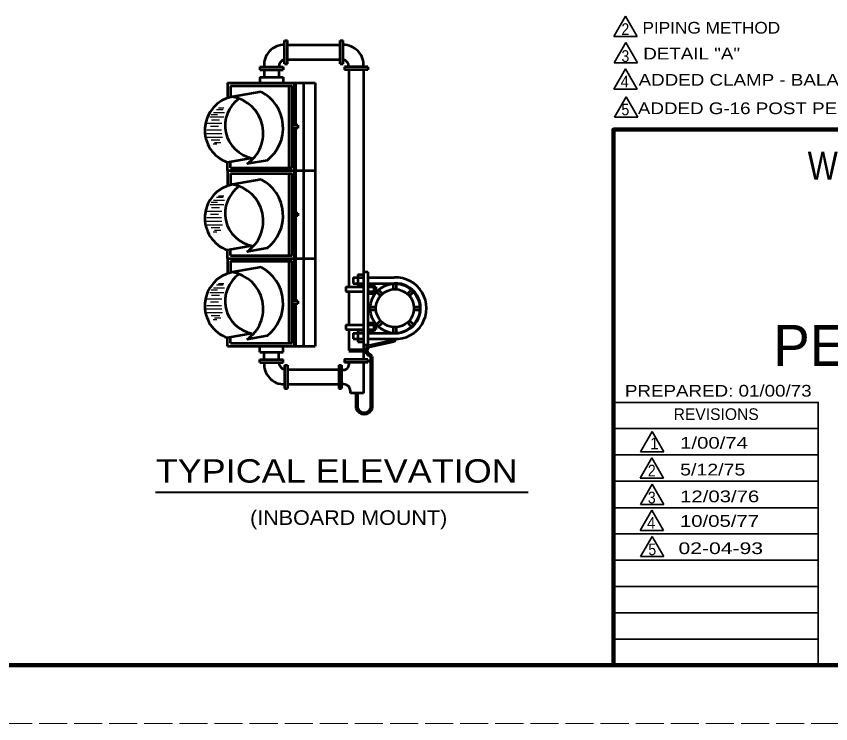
# Model space of a CAD drawing. Extents: x -286 to 394, y -156 to 284.
# Drawn here: x 109 to 248.2, y -155.6 to -34.6 of the extents above; entities that cross this region are included whole.
import ezdxf
from ezdxf.enums import TextEntityAlignment as Align

# ---------------------------------------------------------------- set-up
doc = ezdxf.new("R2010")
doc.units = 0
doc.header["$LTSCALE"] = 0.8
doc.linetypes.add('LONG_DASHED', pattern=[7.5, 6, -1.5])
doc.layers.add('1', color=7, linetype='Continuous', lineweight=53)
doc.layers.add('61', color=7, linetype='Continuous', lineweight=35)

msp = doc.modelspace()

# ---------------------------------------------------------------- linework, layer by layer
at = {"layer": '1', "lineweight": 35}
for p, q in [((213.1055, -34.6416), (211.1055, -38.1057)), ((213.1055, -34.6416), (215.1055, -38.1057)), ((211.1055, -38.1057), (215.1055, -38.1057)), ((213.1387, -39.1506), (211.1387, -42.6147)), ((213.1387, -39.1506), (215.1387, -42.6147)), ((211.1387, -42.6147), (215.1387, -42.6147)), ((213.1055, -43.6264), (211.1055, -47.0905)), ((213.1055, -43.6264), (215.1055, -47.0905)), ((211.1055, -47.0905), (215.1055, -47.0905)), ((213.203, -48.403), (211.203, -51.8671)), ((213.203, -48.403), (215.203, -51.8671)), ((211.203, -51.8671), (215.203, -51.8671)), ((246.0509, -105.1372), (211.0709, -105.1372)), ((217.6545, -105.633), (215.6545, -109.0971)), ((217.6545, -105.633), (219.6545, -109.0971)), ((246.0509, -109.6372), (211.0709, -109.6372)), ((215.6545, -109.0971), (219.6545, -109.0971)), ((217.6214, -110.1088), (215.6214, -113.5729)), ((217.6214, -110.1088), (219.6214, -113.5729)), ((246.0509, -114.1372), (211.0709, -114.1372)), ((215.6214, -113.5729), (219.6214, -113.5729)), ((217.6547, -114.6178), (215.6547, -118.0819)), ((217.6547, -114.6178), (219.6547, -118.0819)), ((215.6547, -118.0819), (219.6547, -118.0819)), ((246.0509, -118.6572), (211.0709, -118.6572)), ((217.6214, -119.0937), (215.6214, -122.5577)), ((217.6214, -119.0937), (219.6214, -122.5577)), ((246.0509, -123.1372), (211.0709, -123.1372)), ((215.6214, -122.5577), (219.6214, -122.5577)), ((217.6825, -123.5532), (215.6825, -127.0173)), ((217.6825, -123.5532), (219.6825, -127.0173)), ((246.0509, -127.6172), (211.0709, -127.6172)), ((215.6825, -127.0173), (219.6825, -127.0173)), ((246.0509, -132.1172), (211.0709, -132.1172)), ((246.0509, -136.6172), (211.0709, -136.6172)), ((246.0509, -141.1372), (211.0709, -141.1372))]:
    msp.add_line(p, q, dxfattribs=at)
at = {"layer": '1'}
for p, q in [((154.826, -42.7785), (154.826, -38.7785)), ((154.826, -38.7785), (155.326, -38.7785)), ((155.326, -42.7785), (155.326, -38.7785)), ((164.326, -42.7785), (164.326, -38.7785)), ((164.326, -42.7785), (164.326, -38.7785)), ((164.326, -38.7785), (164.826, -38.7785)), ((164.826, -42.7785), (164.826, -38.7785)), ((155.326, -39.5285), (164.326, -39.5285)), ((154.826, -42.7785), (155.326, -42.7785)), ((155.326, -42.0285), (164.326, -42.0285)), ((164.326, -42.7785), (164.826, -42.7785)), ((150.576, -43.2785), (154.576, -43.2785)), ((150.576, -43.2785), (150.576, -43.7785)), ((150.576, -43.7785), (154.576, -43.7785)), ((151.326, -43.7785), (151.326, -45.0285)), ((153.826, -43.7785), (153.826, -45.0285)), ((154.576, -43.2785), (154.576, -43.7785)), ((169.076, -43.2785), (165.076, -43.2785)), ((165.076, -43.2785), (165.076, -43.7785)), ((169.076, -43.7785), (165.076, -43.7785)), ((165.826, -43.7785), (165.826, -80.9017)), ((168.326, -43.7785), (168.326, -93.3017)), ((169.076, -43.2785), (169.076, -43.7785)), ((150.576, -45.0285), (154.576, -45.0285)), ((150.576, -45.0285), (150.576, -46.0285)), ((154.576, -45.0285), (154.576, -46.0285)), ((145.076, -46.0285), (160.076, -46.0285)), ((145.076, -46.0285), (145.076, -48.5944)), ((145.576, -46.5285), (156.076, -46.5285)), ((145.576, -46.5285), (145.576, -48.4608)), ((155.576, -46.5285), (155.576, -60.5285)), ((156.076, -46.5285), (156.076, -60.5285)), ((158.076, -46.0285), (158.076, -91.0285)), ((160.076, -46.0285), (160.076, -91.0285)), ((150.826, -47.5285), (145.902, -48.3967)), ((157.076, -53.2785), (156.076, -53.2785)), ((157.076, -53.7785), (156.076, -53.7785)), ((157.076, -53.2785), (157.076, -53.7785)), ((149.247, -58.8807), (145.076, -59.6162)), ((145.076, -61.0285), (145.076, -59.6162)), ((145.576, -60.5285), (145.576, -59.528)), ((151.826, -59.2785), (148.3792, -59.8862)), ((145.076, -61.0285), (160.076, -61.0285)), ((145.076, -61.0285), (145.076, -63.6202)), ((145.576, -60.5285), (156.076, -60.5285)), ((145.576, -61.5285), (156.076, -61.5285)), ((145.576, -61.5285), (145.576, -63.4694)), ((150.826, -62.5285), (145.902, -63.3967)), ((155.576, -61.5285), (155.576, -75.5285)), ((156.076, -61.5285), (156.076, -75.5285)), ((157.076, -68.2785), (156.076, -68.2785)), ((157.076, -68.7785), (156.076, -68.7785)), ((157.076, -68.2785), (157.076, -68.7785)), ((149.247, -73.8807), (145.076, -74.6162)), ((145.076, -76.0285), (145.076, -74.6162)), ((145.576, -75.5285), (145.576, -74.528)), ((151.826, -74.2785), (148.3792, -74.8863)), ((145.076, -76.0285), (160.076, -76.0285)), ((145.076, -76.0285), (145.076, -78.6202)), ((145.576, -75.5285), (156.076, -75.5285)), ((145.576, -76.5285), (156.076, -76.5285)), ((145.576, -76.5285), (145.576, -78.4694)), ((155.576, -76.5285), (155.576, -90.5285)), ((156.076, -76.5285), (156.076, -90.5285)), ((150.826, -77.5285), (145.902, -78.3967)), ((166.576, -79.3017), (166.576, -80.3017)), ((166.576, -79.3017), (168.326, -79.3017)), ((167.326, -78.8017), (168.326, -78.8017)), ((167.326, -78.8017), (167.326, -80.8017)), ((168.326, -78.3017), (169.076, -78.3017)), ((169.076, -78.3017), (169.076, -90.8017)), ((169.076, -79.3017), (173.576, -79.3017)), ((166.576, -80.3017), (168.326, -80.3017)), ((169.076, -80.3017), (173.576, -80.3017)), ((169.076, -80.5517), (170.076, -80.5517)), ((170.076, -80.5517), (170.076, -82.0517)), ((173.4597, -81.3007), (173.4597, -80.3228)), ((173.9597, -81.3007), (173.9597, -80.3228)), ((165.326, -80.9017), (168.326, -80.9017)), ((165.326, -80.9017), (165.326, -81.7017)), ((165.326, -81.7017), (168.326, -81.7017)), ((165.826, -81.7017), (165.826, -87.4017)), ((167.326, -80.8017), (168.326, -80.8017)), ((169.076, -80.9017), (170.426, -80.9017)), ((169.076, -81.7017), (170.426, -81.7017)), ((169.076, -82.0517), (170.076, -82.0517)), ((170.426, -80.9017), (170.426, -81.7017)), ((171.2233, -82.4184), (170.5351, -81.7303)), ((171.5768, -82.0648), (170.8887, -81.3768)), ((175.8154, -82.0815), (176.5245, -81.3763)), ((176.168, -82.4361), (176.8771, -81.7309)), ((157.076, -83.2785), (156.076, -83.2785)), ((157.076, -83.2785), (157.076, -83.7785)), ((157.076, -83.7785), (156.076, -83.7785)), ((169.4597, -84.3017), (170.4373, -84.3017)), ((169.4597, -84.8017), (170.4373, -84.8017)), ((176.9373, -84.3017), (177.9596, -84.3017)), ((176.9373, -84.8017), (177.9596, -84.8017)), ((165.326, -87.4017), (168.326, -87.4017)), ((165.326, -87.4017), (165.326, -88.2017)), ((169.076, -87.0517), (170.076, -87.0517)), ((169.076, -87.4017), (170.426, -87.4017)), ((170.076, -87.0517), (170.076, -88.5517)), ((170.426, -87.4017), (170.426, -88.2017)), ((170.4977, -87.37), (171.2066, -86.665)), ((170.8502, -87.7246), (171.5592, -87.0196)), ((176.5496, -87.7433), (175.8201, -87.014)), ((176.903, -87.3897), (176.1735, -86.6604)), ((149.247, -88.8807), (145.076, -89.6162)), ((165.326, -88.2017), (168.326, -88.2017)), ((165.826, -88.2017), (165.826, -91.7998)), ((166.576, -88.8017), (166.576, -89.8017)), ((166.576, -88.8017), (168.326, -88.8017)), ((167.326, -88.3017), (167.326, -90.3017)), ((167.326, -88.3017), (168.326, -88.3017)), ((169.076, -88.2017), (170.426, -88.2017)), ((169.076, -88.5517), (170.076, -88.5517)), ((169.076, -88.8017), (173.576, -88.8017)), ((173.4597, -88.8228), (173.4597, -87.8005)), ((173.9597, -88.8228), (173.9597, -87.8005)), ((145.076, -91.0285), (145.076, -89.6162)), ((145.576, -90.5285), (145.576, -89.528)), ((151.826, -89.2785), (148.3792, -89.8863)), ((166.576, -89.8017), (168.326, -89.8017)), ((167.326, -90.3017), (168.326, -90.3017)), ((169.076, -89.8017), (173.576, -89.8017)), ((145.076, -91.0285), (160.076, -91.0285)), ((145.576, -90.5285), (156.076, -90.5285)), ((150.576, -92.0495), (150.576, -91.0495)), ((154.576, -92.0495), (154.576, -91.0495)), ((168.326, -90.8017), (169.076, -90.8017)), ((150.576, -92.0495), (154.576, -92.0495)), ((151.326, -93.2995), (151.326, -92.0495)), ((153.826, -93.2995), (153.826, -92.0495)), ((150.576, -93.2995), (154.576, -93.2995)), ((150.576, -93.7995), (150.576, -93.2995)), ((150.576, -93.7995), (154.576, -93.7995)), ((154.576, -93.7995), (154.576, -93.2995)), ((154.826, -94.2995), (154.826, -98.2995)), ((154.826, -94.2995), (155.326, -94.2995)), ((155.326, -94.2995), (155.326, -98.2995)), ((164.0757, -94.2993), (164.0757, -98.2993)), ((164.0757, -94.2993), (164.5757, -94.2993)), ((164.5757, -94.2993), (164.5757, -98.2993)), ((169.0757, -93.8021), (165.0757, -93.7993)), ((168.3257, -93.8016), (168.3222, -99.0514)), ((169.076, -93.3022), (169.0757, -93.8021)), ((155.326, -95.0495), (164.0757, -95.0495)), ((154.826, -98.2995), (155.326, -98.2995)), ((155.326, -97.5495), (164.0757, -97.5495)), ((164.0757, -98.2993), (164.5757, -98.2993)), ((168.3222, -99.0514), (166.0722, -99.0514))]:
    msp.add_line(p, q, dxfattribs=at)
at = {"layer": '1', "lineweight": 90}
for p, q in [((156.576, -46.0285), (156.576, -53.2785)), ((156.576, -53.7785), (156.576, -68.2785)), ((156.576, -68.7785), (156.576, -83.2785)), ((156.576, -83.7785), (156.576, -91.0285))]:
    msp.add_line(p, q, dxfattribs=at)
at = {"layer": '1', "lineweight": 25}
for p, q in [((142.299, -51.4111), (143.3644, -51.4111)), ((142.6637, -51.0767), (144.5599, -51.0767)), ((143.1803, -50.5598), (144.3417, -50.5598)), ((143.5147, -50.3167), (144.4612, -50.3167)), ((142.0559, -51.8367), (144.4334, -51.8367)), ((142.3294, -52.3231), (143.7277, -52.3231)), ((141.5088, -54.056), (144.033, -54.056)), ((141.5392, -52.9312), (144.1253, -52.9312)), ((142.1774, -53.4479), (143.515, -53.4479)), ((141.4177, -54.664), (144.0923, -54.664)), ((141.4177, -55.3024), (144.2336, -55.3024)), ((142.2498, -55.7762), (143.7624, -55.7762)), ((142.6457, -56.4692), (143.2396, -56.4692)), ((142.8189, -56.197), (143.9368, -56.197)), ((143.5147, -65.3167), (144.4612, -65.3167)), ((142.299, -66.4111), (143.3644, -66.4111)), ((142.6637, -66.0767), (144.5599, -66.0767)), ((143.1803, -65.5598), (144.3417, -65.5598)), ((141.5392, -67.9312), (144.1253, -67.9312)), ((142.0559, -66.8367), (144.4334, -66.8367)), ((142.3294, -67.3231), (143.7277, -67.3231)), ((141.5088, -69.056), (144.033, -69.056)), ((142.1774, -68.4479), (143.515, -68.4479)), ((141.4177, -69.664), (144.0923, -69.664)), ((141.4177, -70.3024), (144.2336, -70.3024)), ((142.2498, -70.7763), (143.7624, -70.7763)), ((142.6457, -71.4693), (143.2396, -71.4693)), ((142.8189, -71.197), (143.9368, -71.197)), ((143.1803, -80.5598), (144.3417, -80.5598)), ((143.5147, -80.3167), (144.4612, -80.3167)), ((142.0559, -81.8367), (144.4334, -81.8367)), ((142.299, -81.4111), (143.3644, -81.4111)), ((142.6637, -81.0767), (144.5599, -81.0767)), ((141.5392, -82.9312), (144.1253, -82.9312)), ((142.1774, -83.4479), (143.515, -83.4479)), ((142.3294, -82.3231), (143.7277, -82.3231)), ((141.4177, -84.664), (144.0923, -84.664)), ((141.5088, -84.056), (144.033, -84.056)), ((141.4177, -85.3024), (144.2336, -85.3024)), ((142.2498, -85.7762), (143.7624, -85.7762)), ((142.8189, -86.197), (143.9368, -86.197)), ((142.6457, -86.4693), (143.2396, -86.4693))]:
    msp.add_line(p, q, dxfattribs=at)
at = {"layer": '1', "lineweight": 106}
for p, q in [((169.3262, -91.052), (173.475, -90.1516)), ((169.6972, -101.5514), (169.6972, -92.8023)), ((167.1972, -101.5514), (167.1972, -99.0514))]:
    msp.add_line(p, q, dxfattribs=at)
at = {"layer": '1', "lineweight": 158}
msp.add_line((168.8262, -91.802), (165.826, -91.7998), dxfattribs=at)
at = {"layer": '1', "lineweight": 40}
msp.add_line((132.7564, -116.0136), (196.4497, -116.0136), dxfattribs=at)
at = {"layer": '1', "lineweight": 158}
msp.add_lwpolyline([(211.0509, -145.5772), (211.0509, -53.9973), (382.7109, -53.9973)], dxfattribs=at)
at = {"layer": '1'}
msp.add_lwpolyline([(169.076, -93.3022), (165.076, -93.2993), (165.0757, -93.7993)], dxfattribs=at)
at = {"layer": '1', "lineweight": 35}
msp.add_lwpolyline([(246.0509, -145.6172), (246.0509, -100.6572), (211.0709, -100.6572)], dxfattribs=at)
at = {"layer": '1'}
for centre, radius in [((173.7097, -84.5728), 4.25), ((173.6873, -84.5506), 3.25)]:
    msp.add_circle(centre, radius, dxfattribs=at)
for centre, radius, start, end in [((154.7617, -42.9768), 3.4489, 88.93093, 185.01894), ((164.8903, -42.9768), 3.4489, 354.98106, 91.06907), ((155.2154, -43.3651), 1.3921, 106.24508, 176.43531), ((164.4366, -43.3651), 1.3921, 3.56469, 73.75492), ((147.0065, -54.1182), 5.827, 100.9259, 250.65279), ((150.3335, -53.3206), 5.6653, 125.42652, 258.94304), ((144.8452, -54.6364), 6.3285, 303.94628, 80.38748), ((147.5926, -53.7212), 6.986, 307.29917, 62.42986), ((147.5926, -68.7212), 6.986, 307.29917, 62.42986), ((147.0065, -69.1182), 5.827, 100.9259, 250.65279), ((150.3335, -68.3206), 5.6653, 125.42652, 258.94304), ((144.8452, -69.6364), 6.3285, 303.94628, 80.38748), ((147.5926, -83.7212), 6.986, 307.29917, 62.42986), ((147.0065, -84.1182), 5.827, 100.9259, 250.65279), ((150.3335, -83.3206), 5.6653, 125.42652, 258.94304), ((144.8452, -84.6364), 6.3285, 303.94628, 80.38748), ((173.8203, -84.5517), 5.2557, 267.33556, 92.66444), ((173.8191, -84.5517), 4.2569, 266.72684, 93.27315), ((154.7617, -94.1012), 3.4489, 174.98106, 271.06907), ((155.2154, -93.7129), 1.3921, 183.56469, 253.75492), ((164.8652, -94.089), 1.003, 253.22176, 16.76297), ((164.8688, -98.7538), 1.2396, 346.10771, 103.67892)]:
    msp.add_arc(centre, radius, start, end, dxfattribs=at)
at = {"layer": '1', "lineweight": 106}
for centre, radius, start, end in [((173.4121, -89.9439), 0.217, 286.84777, 40.95171), ((169.6387, -91.802), 0.8125, 112.61986, 247.38013), ((169.2725, -93.0317), 0.4827, 28.38312, 83.61532), ((168.4472, -101.2702), 1.2812, 192.68038, 347.31962)]:
    msp.add_arc(centre, radius, start, end, dxfattribs=at)
at = {"layer": '61', "lineweight": 158}
msp.add_line((382.7109, -145.5772), (-256.3491, -145.5572), dxfattribs=at)
at = {"layer": '61', "linetype": 'LONG_DASHED', "lineweight": 13}
msp.add_line((393.6509, -155.5572), (-286.4091, -155.5772), dxfattribs=at)

# ---------------------------------------------------------------- texts
at = {"layer": '1'}
for s, height, width, p in [('2', 2, 0.9, (213.0793, -37.8386)), ('PIPING METHOD', 2, 1.1, (227.7735, -37.6032)), ('DETAIL "A"', 2, 1.2, (224.4146, -42.0243)), ('3', 2, 0.9, (213.0793, -42.447)), ('ADDED CLAMP - BALANCE ADJUSTER AND CHANGED NOTE 2', 2, 1.2, (263.3085, -46.5045)), ('4', 2, 0.95, (212.9798, -46.7903)), ('5', 2, 0.9, (213.0773, -51.5668)), ('ADDED G-16 POST PED POST MOUNT DETAILS AND ATTENDANT NOTE 4, RENAMED SHEET', 2, 1.2, (286.5495, -51.3691)), ('WEST VIRGINIA DIVISION OF HIGHWAYS', 4.795, 0.85, (297.6993, -62.5972)), ('TYPICAL ELEVATION', 4, 1.15, (163.7346, -114.3628)), ('2', 2, 0.9, (217.5952, -113.3058)), ('3', 2, 0.9, (217.5952, -117.9142)), ('(INBOARD MOUNT)', 2.5, 1.1, (165.7782, -121.592)), ('4', 2, 0.95, (217.4957, -122.2575)), ('5', 2, 0.9, (217.679, -126.7782)), ('02-04-93', 2, 1.35, (229.3869, -126.5783))]:
    msp.add_text(s, height=height, dxfattribs=dict(at, width=width)).set_placement(p, align=Align.CENTER)
for s, height, p in [('PEDESTRIAN HEADS (G-16)', 6.993, (300.4584, -94.4101)), ('1', 2, (218.0428, -108.6642))]:
    msp.add_text(s, height=height, dxfattribs=at).set_placement(p, align=Align.CENTER)
for s, width, p in [('PREPARED: 01/00/73', 1.2, (213.0109, -99.6572)), ('1/00/74', 1.3, (222.4446, -108.5602)), ('5/12/75', 1.25, (222.4445, -113.1355)), ('12/03/76', 1.3, (222.4446, -117.7108)), ('10/05/77', 1.3, (222.4114, -121.9214))]:
    msp.add_text(s, height=1.998, dxfattribs=dict(at, width=width)).set_placement(p)
msp.add_text('REVISIONS', height=1.998, dxfattribs=at).set_placement((221.3309, -103.6572))

doc.saveas('drawing.dxf')
